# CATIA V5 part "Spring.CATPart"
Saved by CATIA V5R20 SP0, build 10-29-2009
Part number: Spring
Bounding box of the stored display mesh (mm): x -25.05 to 25.048, y -25.049 to 25.048, z 0 to 153.6
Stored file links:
  C:\Users\Ehsan.Fathi\Desktop\Spring.CATPart
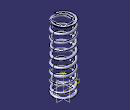
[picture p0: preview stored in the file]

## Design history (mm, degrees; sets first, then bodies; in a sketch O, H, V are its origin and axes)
Body1 (main body)
  Sketch1 on zx-plane, origin (0, 0, 0), H (-1, 0, 0), V (0, 0, 1)
    point P1 (22.2, 0)
  Helix1: Direction Sketch1.V, RefPoint Sketch1, Pitch 18, Height 153.6, TaperAngle 0
  Sketch2 on zx-plane, origin (0, 0, 0), H (-1, 0, 0), V (0, 0, 1)
    circle A1 centre (22.2, 0) radius 2.85
  Rib1: profile Sketch2, centre curve Helix1
  Sketch3 on face of Rib1, origin (1.5253, 1.8378, 0.0556), H (-0.962, -0.2718, -0.0272), V (-0.0211, -0.0251, 0.9995)
    projected circle E1 centre (-24.3464, 152.9656) radius 2.85 from face of Rib1
  Shaft1: profile Sketch3, axis Sketch1.V, angle 250
  Sketch4 on face of Rib1, origin (0, 0, 0), H (-1, 0, 0), V (0, 0, 1)
    projected circle E1 centre (22.2, 0) radius 2.85 from face of Rib1
  Shaft2: profile Sketch4, axis Sketch4.V, angle 0, second angle 250
  Sketch5 on xy-plane, origin (0, 0, 0), H (1, 0, 0), V (0, 1, 0)
    circle A1 centre (0, 0) radius 31.0167
  Pocket1: profile Sketch5, direction (0, 0, -1), length 20
  Plane1: type Offset, RefPlane xy-plane, Offset 153.6
  Sketch6 on Plane1, origin (0, 0, 153.6), H (1, 0, 0), V (0, 1, 0)
    circle A1 centre (0, 0) radius 31.6479
  Pocket2: profile Sketch6, direction (0, 0, 1), length 20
